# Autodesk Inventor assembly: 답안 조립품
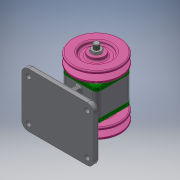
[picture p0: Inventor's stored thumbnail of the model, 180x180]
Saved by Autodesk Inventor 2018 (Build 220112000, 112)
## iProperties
Created: 2020-11
Part Number: 답안 조립품
Document SubType Name: Assembly
Designer: 1class 3
Author: 1class 3
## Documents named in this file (10)
- C:\Users\1class 3\Desktop\701106V1048\답안 조립품.iam
- C:\Users\1class 3\Desktop\701106V1048\본체.ipt
- C:\Users\1class 3\Desktop\701106V1048\V-벨트풀리.ipt
- C:\Users\1class 3\Desktop\701106V1048\너트 M10x1.ipt
- C:\Users\1class 3\Desktop\701106V1048\베어링 6004.ipt
- C:\Users\1class 3\Desktop\701106V1048\볼트 M4.ipt
- C:\Users\1class 3\Desktop\701106V1048\오일 실 17 30 5.ipt
- C:\Users\1class 3\Desktop\701106V1048\축.ipt
- C:\Users\1class 3\Desktop\701106V1048\커버.ipt
- C:\Users\1class 3\Desktop\701106V1048\키 5 x 5 x 12.ipt
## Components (2 placed, 1 different names)
1. V-벨트풀리:1
2. V-벨트풀리:2
